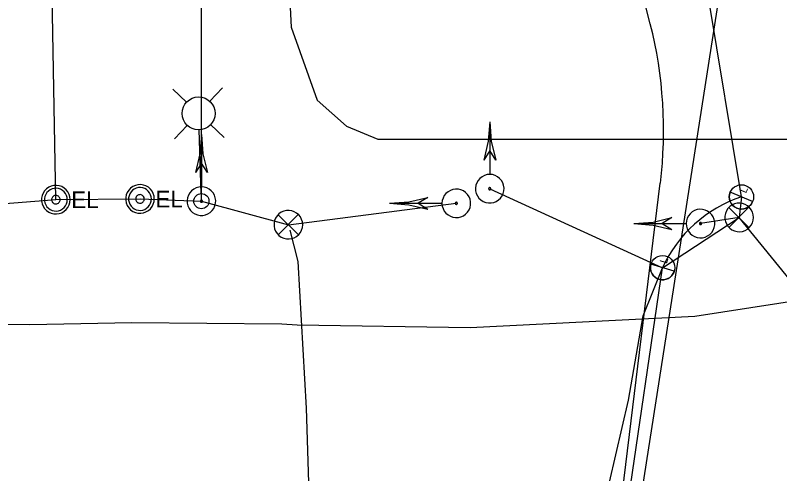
# Model space of a CAD drawing. Extents: x 600849 to 606371, y 330010 to 403088.
# Drawn here: x 604364.1 to 604540.4, y 339253 to 339358.8 of the extents above; entities that cross this region are included whole.
import ezdxf

# ---------------------------------------------------------------- set-up
doc = ezdxf.new("R2010")
doc.units = 0
for name, color, linetype in [('E_FTMS_Conduit', 7, 'Continuous'), ('E_LTG', 7, 'Continuous'), ('E_LTG_CID', 7, 'Continuous'), ('E_LTG_LP', 7, 'Continuous'), ('E_SIG', 7, 'Continuous'), ('E_SIG_Conduit', 7, 'Continuous'), ('E_UTL_E', 7, 'Continuous'), ('E_UTL_FO_UG', 7, 'Continuous'), ('E_UTL_FO_UG_MWFN', 7, 'Continuous'), ('E_UTL_T_UG', 7, 'Continuous')]:
    doc.layers.add(name, color=color, linetype=linetype)

# ---------------------------------------------------------------- blocks, each defined once
blk = doc.blocks.new('_U274')
at = {"layer": 'E_LTG'}
blk.add_lwpolyline([(0.001, -0.171), (0.001, 0.172)], dxfattribs=at)
blk.add_circle((0.001, 0), 0.171, dxfattribs=at)
blk.add_arc((0.001, 0), 0.171, 90, 270, dxfattribs=at)
blk.add_text('L', height=0.108, dxfattribs=at).set_placement((0.066, -0.042))
blk = doc.blocks.new('_U275')
at = {"layer": 'E_LTG'}
blk.add_lwpolyline([(0.001, -0.171), (0.001, 0.172)], dxfattribs=at)
blk.add_circle((0.001, 0), 0.171, dxfattribs=at)
blk.add_arc((0.001, 0), 0.171, 90, 270, dxfattribs=at)
blk.add_text('L', height=0.108, dxfattribs=at).set_placement((0.066, -0.042))
blk = doc.blocks.new('_U282')
at = {"layer": 'E_LTG_LP'}
for p, q in [((-0.0745, 0.6368), (-0.1589, 0.7212)), ((0.0745, 0.6368), (0.1589, 0.7212)), ((-0.0745, 0.4877), (-0.1589, 0.4033)), ((0, 0.0484), (0, 0.4568)), ((0.0745, 0.4877), (0.1589, 0.4033))]:
    blk.add_line(p, q, dxfattribs=at)
for centre, radius in [((0, 0.5622), 0.1054), ((0, 0), 0.0484)]:
    blk.add_circle(centre, radius, dxfattribs=at)

msp = doc.modelspace()

# ---------------------------------------------------------------- linework, layer by layer
at = {"layer": 'E_FTMS_Conduit'}
msp.add_lwpolyline([(604487.12, 339110.95), (604528.77, 339378.34)], dxfattribs=at)
at = {"layer": 'E_LTG_CID'}
msp.add_line((604406.99, 339315.86), (604406.95, 339427.62), dxfattribs=at)
for points in [[(604128.43, 339305.76), (604251.21, 339306.56), (604373.42, 339316.22), (604373.42, 339316.22)], [(604462.53, 338665.89), (604459.42, 338679.36), (604459.39, 338681.9), (604459.7, 338688.71), (604460.81, 338741.12), (604464.5, 338801.96), (604467.28, 338847.26), (604471.84, 338867.78), (604472.52, 338869.57), (604471.92, 338904.85), (604477.27, 339004.79), (604479.36, 339028.67), (604475.85, 339040.45), (604483.83, 339111.42), (604496.92, 339188.17), (604513.35, 339300.5)], [(604472.34, 339048.39), (604473.46, 339063.32), (604479.45, 339117.63), (604486.02, 339161.45), (604495.8, 339218.5), (604495.95, 339219.98), (604495.31, 339225.73), (604505.5, 339269.91), (604508.87, 339289.37), (604513.35, 339300.5)]]:
    msp.add_lwpolyline(points, dxfattribs=at)
msp.add_arc((604541.08, 339287.91), 30.46, 108.2691, 155.5801, dxfattribs=at)
at = {"layer": 'E_SIG'}
for points in [[(604473.49, 339334.15), (604473.15, 339329.69), (604472.12, 339325.35)], [(604473.49, 339334.15), (604473.49, 339322.11)], [(604473.49, 339334.15), (604473.84, 339329.69), (604474.87, 339325.35)], [(604406.99, 339331.26), (604406.65, 339326.81), (604405.62, 339322.46)], [(604406.99, 339331.26), (604406.99, 339319.22)], [(604406.99, 339331.26), (604407.34, 339326.81), (604408.37, 339322.46)], [(604473.49, 339327.55), (604472.12, 339325.35)], [(604474.87, 339325.35), (604473.49, 339327.55)], [(604406.99, 339324.66), (604405.62, 339322.46)], [(604408.36, 339322.46), (604406.99, 339324.66)], [(604473.49, 339322.05), (604472.87, 339321.99), (604472.27, 339321.81), (604471.71, 339321.52), (604471.22, 339321.14), (604470.81, 339320.66), (604470.49, 339320.12), (604470.29, 339319.53), (604470.2, 339318.9), (604470.23, 339318.28), (604470.38, 339317.67), (604470.64, 339317.1), (604471, 339316.59), (604471.45, 339316.15), (604471.98, 339315.81), (604472.56, 339315.58), (604473.18, 339315.46), (604473.81, 339315.46), (604474.42, 339315.58), (604475.01, 339315.81), (604475.53, 339316.15), (604475.99, 339316.59), (604476.35, 339317.1), (604476.61, 339317.67), (604476.76, 339318.28), (604476.79, 339318.9), (604476.7, 339319.53), (604476.5, 339320.12), (604476.18, 339320.66), (604475.77, 339321.14), (604475.28, 339321.52), (604474.72, 339321.81), (604474.12, 339321.99), (604473.49, 339322.05)], [(604406.99, 339319.16), (604406.37, 339319.1), (604405.77, 339318.93), (604405.21, 339318.64), (604404.71, 339318.25), (604404.3, 339317.78), (604403.99, 339317.24), (604403.78, 339316.64), (604403.7, 339316.02), (604403.73, 339315.39), (604403.87, 339314.78), (604404.13, 339314.21), (604404.5, 339313.7), (604404.95, 339313.27), (604405.48, 339312.93), (604406.06, 339312.7), (604406.68, 339312.58), (604407.31, 339312.58), (604407.92, 339312.7), (604408.5, 339312.93), (604409.03, 339313.27), (604409.49, 339313.7), (604409.85, 339314.21), (604410.11, 339314.78), (604410.26, 339315.39), (604410.29, 339316.02), (604410.2, 339316.64), (604409.99, 339317.24), (604409.68, 339317.78), (604409.27, 339318.25), (604408.78, 339318.64), (604408.22, 339318.93), (604407.62, 339319.1), (604406.99, 339319.16)], [(604462.48, 339315.37), (604462.54, 339314.74), (604462.72, 339314.14), (604463, 339313.58), (604463.39, 339313.09), (604463.87, 339312.68), (604464.41, 339312.37), (604465, 339312.16), (604465.62, 339312.07), (604466.25, 339312.1), (604466.86, 339312.25), (604467.43, 339312.51), (604467.94, 339312.87), (604468.37, 339313.33), (604468.71, 339313.86), (604468.95, 339314.44), (604469.07, 339315.05), (604469.07, 339315.68), (604468.95, 339316.3), (604468.71, 339316.88), (604468.37, 339317.41), (604467.94, 339317.86), (604467.43, 339318.23), (604466.86, 339318.49), (604466.25, 339318.63), (604465.62, 339318.66), (604465, 339318.57), (604464.41, 339318.37), (604463.87, 339318.06), (604463.39, 339317.65), (604463, 339317.15), (604462.72, 339316.59), (604462.54, 339315.99), (604462.48, 339315.37)], [(604473.49, 339319), (604473.45, 339319), (604473.4, 339318.98), (604473.36, 339318.96), (604473.32, 339318.93), (604473.29, 339318.89), (604473.26, 339318.85), (604473.25, 339318.81), (604473.24, 339318.76), (604473.24, 339318.71), (604473.26, 339318.66), (604473.27, 339318.62), (604473.3, 339318.58), (604473.34, 339318.55), (604473.38, 339318.52), (604473.42, 339318.5), (604473.47, 339318.5), (604473.52, 339318.5), (604473.56, 339318.5), (604473.61, 339318.52), (604473.65, 339318.55), (604473.68, 339318.58), (604473.71, 339318.62), (604473.73, 339318.66), (604473.74, 339318.71), (604473.75, 339318.76), (604473.74, 339318.81), (604473.72, 339318.85), (604473.7, 339318.89), (604473.67, 339318.93), (604473.63, 339318.96), (604473.59, 339318.98), (604473.54, 339319), (604473.49, 339319)], [(604406.99, 339316.12), (604406.94, 339316.11), (604406.9, 339316.1), (604406.86, 339316.08), (604406.82, 339316.05), (604406.79, 339316.01), (604406.76, 339315.97), (604406.75, 339315.92), (604406.74, 339315.88), (604406.74, 339315.83), (604406.75, 339315.78), (604406.77, 339315.74), (604406.8, 339315.7), (604406.84, 339315.67), (604406.88, 339315.64), (604406.92, 339315.62), (604406.97, 339315.61), (604407.02, 339315.61), (604407.06, 339315.62), (604407.11, 339315.64), (604407.15, 339315.67), (604407.18, 339315.7), (604407.21, 339315.74), (604407.23, 339315.78), (604407.24, 339315.83), (604407.24, 339315.88), (604407.24, 339315.92), (604407.22, 339315.97), (604407.2, 339316.01), (604407.17, 339316.05), (604407.13, 339316.08), (604407.09, 339316.1), (604407.04, 339316.11), (604406.99, 339316.12)], [(604450.38, 339315.37), (604454.83, 339315.71), (604459.18, 339316.74)], [(604459.18, 339316.74), (604456.98, 339315.37)], [(604450.38, 339315.37), (604462.42, 339315.37)], [(604450.38, 339315.37), (604454.83, 339315.02), (604459.18, 339313.99)], [(604456.98, 339315.37), (604459.18, 339313.99)], [(604465.53, 339315.37), (604465.53, 339315.32), (604465.55, 339315.27), (604465.57, 339315.23), (604465.6, 339315.19), (604465.63, 339315.16), (604465.68, 339315.14), (604465.72, 339315.12), (604465.77, 339315.12), (604465.82, 339315.12), (604465.86, 339315.13), (604465.91, 339315.15), (604465.95, 339315.18), (604465.98, 339315.21), (604466, 339315.25), (604466.02, 339315.3), (604466.03, 339315.34), (604466.03, 339315.39), (604466.02, 339315.44), (604466, 339315.48), (604465.98, 339315.52), (604465.95, 339315.56), (604465.91, 339315.59), (604465.86, 339315.61), (604465.82, 339315.62), (604465.77, 339315.62), (604465.72, 339315.61), (604465.68, 339315.6), (604465.63, 339315.57), (604465.6, 339315.54), (604465.57, 339315.5), (604465.55, 339315.46), (604465.53, 339315.42), (604465.53, 339315.37)], [(604534.31, 339312.11), (604534.25, 339312.74), (604534.07, 339313.34), (604533.79, 339313.9), (604533.4, 339314.39), (604532.93, 339314.8), (604532.38, 339315.11), (604531.79, 339315.32), (604531.17, 339315.41), (604530.54, 339315.38), (604529.93, 339315.23), (604529.36, 339314.97), (604528.85, 339314.61), (604528.42, 339314.15), (604528.08, 339313.62), (604527.84, 339313.04), (604527.73, 339312.43), (604527.73, 339311.8), (604527.84, 339311.18), (604528.08, 339310.6), (604528.42, 339310.07), (604528.85, 339309.62), (604529.36, 339309.25), (604529.93, 339308.99), (604530.54, 339308.85), (604531.17, 339308.82), (604531.79, 339308.9), (604532.38, 339309.11), (604532.93, 339309.42), (604533.4, 339309.83), (604533.79, 339310.33), (604534.07, 339310.89), (604534.25, 339311.49), (604534.31, 339312.11)], [(604533.27, 339314.45), (604528.66, 339309.79)], [(604528.66, 339314.4), (604533.32, 339309.75)], [(604430.35, 339310.44), (604430.29, 339311.07), (604430.11, 339311.67), (604429.82, 339312.22), (604429.43, 339312.72), (604428.96, 339313.13), (604428.42, 339313.44), (604427.82, 339313.65), (604427.2, 339313.74), (604426.58, 339313.71), (604425.97, 339313.56), (604425.4, 339313.3), (604424.88, 339312.93), (604424.45, 339312.48), (604424.11, 339311.95), (604423.88, 339311.37), (604423.76, 339310.75), (604423.76, 339310.13), (604423.88, 339309.51), (604424.11, 339308.93), (604424.45, 339308.4), (604424.88, 339307.95), (604425.4, 339307.58), (604425.97, 339307.32), (604426.58, 339307.17), (604427.2, 339307.14), (604427.82, 339307.23), (604428.42, 339307.44), (604428.96, 339307.75), (604429.43, 339308.16), (604429.82, 339308.66), (604430.11, 339309.21), (604430.29, 339309.82), (604430.35, 339310.44)], [(604429.31, 339312.78), (604424.7, 339308.12)], [(604424.7, 339312.73), (604429.35, 339308.07)], [(604518.8, 339310.71), (604518.86, 339310.08), (604519.04, 339309.48), (604519.33, 339308.92), (604519.72, 339308.43), (604520.19, 339308.02), (604520.73, 339307.7), (604521.33, 339307.5), (604521.95, 339307.41), (604522.57, 339307.44), (604523.18, 339307.59), (604523.75, 339307.85), (604524.27, 339308.21), (604524.7, 339308.67), (604525.04, 339309.19), (604525.27, 339309.78), (604525.39, 339310.39), (604525.39, 339311.02), (604525.27, 339311.64), (604525.04, 339312.22), (604524.7, 339312.75), (604524.27, 339313.2), (604523.75, 339313.56), (604523.18, 339313.82), (604522.57, 339313.97), (604521.95, 339314), (604521.33, 339313.91), (604520.73, 339313.71), (604520.19, 339313.39), (604519.72, 339312.98), (604519.33, 339312.49), (604519.04, 339311.93), (604518.86, 339311.33), (604518.8, 339310.71)], [(604506.7, 339310.71), (604511.16, 339311.05), (604515.5, 339312.08)], [(604506.7, 339310.71), (604518.75, 339310.71)], [(604506.7, 339310.71), (604511.16, 339310.36), (604515.5, 339309.33)], [(604515.5, 339312.08), (604513.3, 339310.71)], [(604513.3, 339310.71), (604515.5, 339309.33)], [(604521.85, 339310.71), (604521.86, 339310.66), (604521.87, 339310.61), (604521.89, 339310.57), (604521.92, 339310.53), (604521.96, 339310.5), (604522, 339310.48), (604522.04, 339310.46), (604522.09, 339310.45), (604522.14, 339310.46), (604522.19, 339310.47), (604522.23, 339310.49), (604522.27, 339310.52), (604522.3, 339310.55), (604522.33, 339310.59), (604522.35, 339310.63), (604522.36, 339310.68), (604522.36, 339310.73), (604522.35, 339310.78), (604522.33, 339310.82), (604522.3, 339310.86), (604522.27, 339310.9), (604522.23, 339310.92), (604522.19, 339310.94), (604522.14, 339310.96), (604522.09, 339310.96), (604522.04, 339310.95), (604522, 339310.94), (604521.96, 339310.91), (604521.92, 339310.88), (604521.89, 339310.84), (604521.87, 339310.8), (604521.86, 339310.75), (604521.85, 339310.71)], [(604531.01, 339312.11), (604522.1, 339310.71)]]:
    msp.add_lwpolyline(points, dxfattribs=at)
at = {"layer": 'E_SIG_Conduit'}
for p, q in [((604531.54, 339316.84), (604521.4, 339378.1)), ((604373.42, 339316.22), (604392.83, 339316.38)), ((604392.83, 339316.38), (604406.99, 339315.86))]:
    msp.add_line(p, q, dxfattribs=at)
for points in [[(604373.42, 339316.22), (604372.49, 339367.58), (604370.88, 339417.7), (604369.15, 339434.44)], [(604473.49, 339318.75), (604513.35, 339300.5)], [(604531.54, 339316.84), (604531.01, 339312.11)], [(604406.99, 339315.86), (604427.05, 339310.44)], [(604427.05, 339310.44), (604465.78, 339315.37)], [(604513.35, 339300.5), (604531.01, 339312.11)], [(604578.49, 339253.88), (604531.01, 339312.11)], [(604437.65, 339088.56), (604437.61, 339089.75), (604435.37, 339154.82), (604433.06, 339209.21), (604431.23, 339268.05), (604429.3, 339301.93), (604427.49, 339309.21)]]:
    msp.add_lwpolyline(points, dxfattribs=at)
at = {"layer": 'E_UTL_E'}
for points in [[(604376.72, 339316.22), (604376.66, 339316.84), (604376.48, 339317.44), (604376.19, 339318), (604375.81, 339318.49), (604375.33, 339318.9), (604374.79, 339319.22), (604374.19, 339319.42), (604373.57, 339319.51), (604372.95, 339319.48), (604372.34, 339319.34), (604371.77, 339319.07), (604371.26, 339318.71), (604370.82, 339318.26), (604370.48, 339317.73), (604370.25, 339317.15), (604370.13, 339316.53), (604370.13, 339315.9), (604370.25, 339315.29), (604370.48, 339314.7), (604370.82, 339314.18), (604371.26, 339313.72), (604371.77, 339313.36), (604372.34, 339313.1), (604372.95, 339312.95), (604373.57, 339312.92), (604374.19, 339313.01), (604374.79, 339313.21), (604375.33, 339313.53), (604375.81, 339313.94), (604376.19, 339314.43), (604376.48, 339314.99), (604376.66, 339315.59), (604376.72, 339316.22)], [(604376.72, 339316.22), (604376.66, 339316.84), (604376.48, 339317.44), (604376.19, 339318), (604375.81, 339318.49), (604375.33, 339318.9), (604374.79, 339319.22), (604374.19, 339319.42), (604373.57, 339319.51), (604372.95, 339319.48), (604372.34, 339319.34), (604371.77, 339319.07), (604371.26, 339318.71), (604370.82, 339318.26), (604370.48, 339317.73), (604370.25, 339317.15), (604370.13, 339316.53), (604370.13, 339315.9), (604370.25, 339315.29), (604370.48, 339314.7), (604370.82, 339314.18), (604371.26, 339313.72), (604371.77, 339313.36), (604372.34, 339313.1), (604372.95, 339312.95), (604373.57, 339312.92), (604374.19, 339313.01), (604374.79, 339313.21), (604375.33, 339313.53), (604375.81, 339313.94), (604376.19, 339314.43), (604376.48, 339314.99), (604376.66, 339315.59), (604376.72, 339316.22)], [(604396.13, 339316.38), (604396.07, 339317.01), (604395.9, 339317.61), (604395.61, 339318.17), (604395.22, 339318.66), (604394.75, 339319.07), (604394.2, 339319.38), (604393.61, 339319.59), (604392.99, 339319.68), (604392.36, 339319.65), (604391.75, 339319.5), (604391.18, 339319.24), (604390.67, 339318.88), (604390.24, 339318.42), (604389.9, 339317.89), (604389.67, 339317.31), (604389.55, 339316.7), (604389.55, 339316.07), (604389.67, 339315.45), (604389.9, 339314.87), (604390.24, 339314.34), (604390.67, 339313.89), (604391.18, 339313.52), (604391.75, 339313.26), (604392.36, 339313.12), (604392.99, 339313.09), (604393.61, 339313.17), (604394.2, 339313.38), (604394.75, 339313.69), (604395.22, 339314.1), (604395.61, 339314.6), (604395.9, 339315.16), (604396.07, 339315.76), (604396.13, 339316.38)], [(604396.13, 339316.38), (604396.07, 339317.01), (604395.9, 339317.61), (604395.61, 339318.17), (604395.22, 339318.66), (604394.75, 339319.07), (604394.2, 339319.38), (604393.61, 339319.59), (604392.99, 339319.68), (604392.36, 339319.65), (604391.75, 339319.5), (604391.18, 339319.24), (604390.67, 339318.88), (604390.24, 339318.42), (604389.9, 339317.89), (604389.67, 339317.31), (604389.55, 339316.7), (604389.55, 339316.07), (604389.67, 339315.45), (604389.9, 339314.87), (604390.24, 339314.34), (604390.67, 339313.89), (604391.18, 339313.52), (604391.75, 339313.26), (604392.36, 339313.12), (604392.99, 339313.09), (604393.61, 339313.17), (604394.2, 339313.38), (604394.75, 339313.69), (604395.22, 339314.1), (604395.61, 339314.6), (604395.9, 339315.16), (604396.07, 339315.76), (604396.13, 339316.38)], [(604376.06, 339316.22), (604376.01, 339316.72), (604375.87, 339317.2), (604375.64, 339317.64), (604375.33, 339318.04), (604374.95, 339318.37), (604374.51, 339318.62), (604374.04, 339318.78), (604373.54, 339318.85), (604373.04, 339318.83), (604372.55, 339318.71), (604372.1, 339318.5), (604371.69, 339318.21), (604371.34, 339317.85), (604371.07, 339317.43), (604370.88, 339316.96), (604370.79, 339316.47), (604370.79, 339315.97), (604370.88, 339315.47), (604371.07, 339315.01), (604371.34, 339314.58), (604371.69, 339314.22), (604372.1, 339313.93), (604372.55, 339313.72), (604373.04, 339313.6), (604373.54, 339313.58), (604374.04, 339313.65), (604374.51, 339313.82), (604374.95, 339314.07), (604375.33, 339314.39), (604375.64, 339314.79), (604375.87, 339315.24), (604376.01, 339315.72), (604376.06, 339316.22)], [(604376.06, 339316.22), (604376.01, 339316.72), (604375.87, 339317.2), (604375.64, 339317.64), (604375.33, 339318.04), (604374.95, 339318.37), (604374.51, 339318.62), (604374.04, 339318.78), (604373.54, 339318.85), (604373.04, 339318.83), (604372.55, 339318.71), (604372.1, 339318.5), (604371.69, 339318.21), (604371.34, 339317.85), (604371.07, 339317.43), (604370.88, 339316.96), (604370.79, 339316.47), (604370.79, 339315.97), (604370.88, 339315.47), (604371.07, 339315.01), (604371.34, 339314.58), (604371.69, 339314.22), (604372.1, 339313.93), (604372.55, 339313.72), (604373.04, 339313.6), (604373.54, 339313.58), (604374.04, 339313.65), (604374.51, 339313.82), (604374.95, 339314.07), (604375.33, 339314.39), (604375.64, 339314.79), (604375.87, 339315.24), (604376.01, 339315.72), (604376.06, 339316.22)], [(604395.47, 339316.38), (604395.42, 339316.88), (604395.28, 339317.36), (604395.05, 339317.81), (604394.74, 339318.2), (604394.36, 339318.53), (604393.93, 339318.78), (604393.45, 339318.95), (604392.96, 339319.02), (604392.46, 339318.99), (604391.97, 339318.88), (604391.51, 339318.67), (604391.1, 339318.38), (604390.76, 339318.01), (604390.49, 339317.59), (604390.3, 339317.13), (604390.2, 339316.63), (604390.2, 339316.13), (604390.3, 339315.64), (604390.49, 339315.17), (604390.76, 339314.75), (604391.1, 339314.39), (604391.51, 339314.1), (604391.97, 339313.89), (604392.46, 339313.77), (604392.96, 339313.74), (604393.45, 339313.82), (604393.93, 339313.98), (604394.36, 339314.23), (604394.74, 339314.56), (604395.05, 339314.95), (604395.28, 339315.4), (604395.42, 339315.88), (604395.47, 339316.38)], [(604395.47, 339316.38), (604395.42, 339316.88), (604395.28, 339317.36), (604395.05, 339317.81), (604394.74, 339318.2), (604394.36, 339318.53), (604393.93, 339318.78), (604393.45, 339318.95), (604392.96, 339319.02), (604392.46, 339318.99), (604391.97, 339318.88), (604391.51, 339318.67), (604391.1, 339318.38), (604390.76, 339318.01), (604390.49, 339317.59), (604390.3, 339317.13), (604390.2, 339316.63), (604390.2, 339316.13), (604390.3, 339315.64), (604390.49, 339315.17), (604390.76, 339314.75), (604391.1, 339314.39), (604391.51, 339314.1), (604391.97, 339313.89), (604392.46, 339313.77), (604392.96, 339313.74), (604393.45, 339313.82), (604393.93, 339313.98), (604394.36, 339314.23), (604394.74, 339314.56), (604395.05, 339314.95), (604395.28, 339315.4), (604395.42, 339315.88), (604395.47, 339316.38)], [(604374.41, 339316.22), (604374.39, 339316.4), (604374.34, 339316.58), (604374.25, 339316.75), (604374.13, 339316.9), (604373.99, 339317.02), (604373.83, 339317.12), (604373.65, 339317.18), (604373.46, 339317.21), (604373.28, 339317.2), (604373.09, 339317.15), (604372.92, 339317.07), (604372.77, 339316.96), (604372.64, 339316.83), (604372.54, 339316.67), (604372.47, 339316.5), (604372.43, 339316.31), (604372.43, 339316.12), (604372.47, 339315.94), (604372.54, 339315.76), (604372.64, 339315.6), (604372.77, 339315.47), (604372.92, 339315.36), (604373.09, 339315.28), (604373.28, 339315.24), (604373.46, 339315.23), (604373.65, 339315.25), (604373.83, 339315.32), (604373.99, 339315.41), (604374.13, 339315.53), (604374.25, 339315.68), (604374.34, 339315.85), (604374.39, 339316.03), (604374.41, 339316.22)], [(604374.41, 339316.22), (604374.39, 339316.4), (604374.34, 339316.58), (604374.25, 339316.75), (604374.13, 339316.9), (604373.99, 339317.02), (604373.83, 339317.12), (604373.65, 339317.18), (604373.46, 339317.21), (604373.28, 339317.2), (604373.09, 339317.15), (604372.92, 339317.07), (604372.77, 339316.96), (604372.64, 339316.83), (604372.54, 339316.67), (604372.47, 339316.5), (604372.43, 339316.31), (604372.43, 339316.12), (604372.47, 339315.94), (604372.54, 339315.76), (604372.64, 339315.6), (604372.77, 339315.47), (604372.92, 339315.36), (604373.09, 339315.28), (604373.28, 339315.24), (604373.46, 339315.23), (604373.65, 339315.25), (604373.83, 339315.32), (604373.99, 339315.41), (604374.13, 339315.53), (604374.25, 339315.68), (604374.34, 339315.85), (604374.39, 339316.03), (604374.41, 339316.22)], [(604393.82, 339316.38), (604393.8, 339316.57), (604393.75, 339316.75), (604393.66, 339316.92), (604393.55, 339317.06), (604393.41, 339317.19), (604393.24, 339317.28), (604393.07, 339317.34), (604392.88, 339317.37), (604392.69, 339317.36), (604392.51, 339317.32), (604392.34, 339317.24), (604392.18, 339317.13), (604392.05, 339316.99), (604391.95, 339316.84), (604391.88, 339316.66), (604391.85, 339316.48), (604391.85, 339316.29), (604391.88, 339316.1), (604391.95, 339315.93), (604392.05, 339315.77), (604392.18, 339315.63), (604392.34, 339315.52), (604392.51, 339315.45), (604392.69, 339315.4), (604392.88, 339315.39), (604393.07, 339315.42), (604393.24, 339315.48), (604393.41, 339315.58), (604393.55, 339315.7), (604393.66, 339315.85), (604393.75, 339316.01), (604393.8, 339316.19), (604393.82, 339316.38)], [(604393.82, 339316.38), (604393.8, 339316.57), (604393.75, 339316.75), (604393.66, 339316.92), (604393.55, 339317.06), (604393.41, 339317.19), (604393.24, 339317.28), (604393.07, 339317.34), (604392.88, 339317.37), (604392.69, 339317.36), (604392.51, 339317.32), (604392.34, 339317.24), (604392.18, 339317.13), (604392.05, 339316.99), (604391.95, 339316.84), (604391.88, 339316.66), (604391.85, 339316.48), (604391.85, 339316.29), (604391.88, 339316.1), (604391.95, 339315.93), (604392.05, 339315.77), (604392.18, 339315.63), (604392.34, 339315.52), (604392.51, 339315.45), (604392.69, 339315.4), (604392.88, 339315.39), (604393.07, 339315.42), (604393.24, 339315.48), (604393.41, 339315.58), (604393.55, 339315.7), (604393.66, 339315.85), (604393.75, 339316.01), (604393.8, 339316.19), (604393.82, 339316.38)]]:
    msp.add_lwpolyline(points, dxfattribs=at)
at = {"layer": 'E_UTL_FO_UG'}
msp.add_lwpolyline([(604426.84, 339372.77), (604427.7, 339356.06), (604433.67, 339339.18), (604440.49, 339333.21), (604447.72, 339330.16), (604677.88, 339330.16), (604802.34, 339330.16)], dxfattribs=at)
at = {"layer": 'E_UTL_FO_UG_MWFN'}
for p, q in [((604510.53, 339356.78), (604485.37, 339456.13)), ((604502.42, 339235.21), (604512.84, 339320.05))]:
    msp.add_line(p, q, dxfattribs=at)
msp.add_arc((604413.59, 339332.24), 100, 352.9983, 14.2099, dxfattribs=at)
at = {"layer": 'E_UTL_T_UG'}
for points in [[(604429.09, 339287.34), (604468.98, 339286.71), (604520.77, 339289.29), (604559.57, 339295.36), (604569.05, 339300.93), (604581.72, 339310.08), (604600.12, 339325.3), (604610.79, 339329.02), (604638.67, 339330), (604640.1, 339329.89)], [(604303.52, 339290.2), (604312.12, 339290.04), (604324.83, 339288.79), (604333.49, 339287.97), (604343.39, 339287.52), (604367.45, 339287.43), (604390.93, 339287.86), (604425.55, 339287.56), (604429.09, 339287.34)]]:
    msp.add_lwpolyline(points, dxfattribs=at)

# ---------------------------------------------------------------- block references
at = {"layer": 'E_LTG_CID'}
for name, p, xscale, yscale, rotation in [('_U282', (604406.99, 339315.86), 36.08916666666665, 36.08916666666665, 1.8279682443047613), ('_U275', (604531.54, 339316.84), 16.404166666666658, 16.404166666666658, 67.07205998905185), ('_U274', (604513.35, 339300.5), 16.404166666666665, 16.40416666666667, 72.88616374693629)]:
    msp.add_blockref(name, p, dxfattribs=dict(at, xscale=xscale, yscale=yscale, rotation=rotation))

# ---------------------------------------------------------------- texts
at = {"layer": 'E_UTL_E'}
for p in [(604376.98, 339314.27), (604376.98, 339314.27), (604396.4, 339314.44), (604396.4, 339314.44)]:
    msp.add_text('EL', height=3.849, dxfattribs=at).set_placement(p)

doc.saveas('drawing.dxf')
